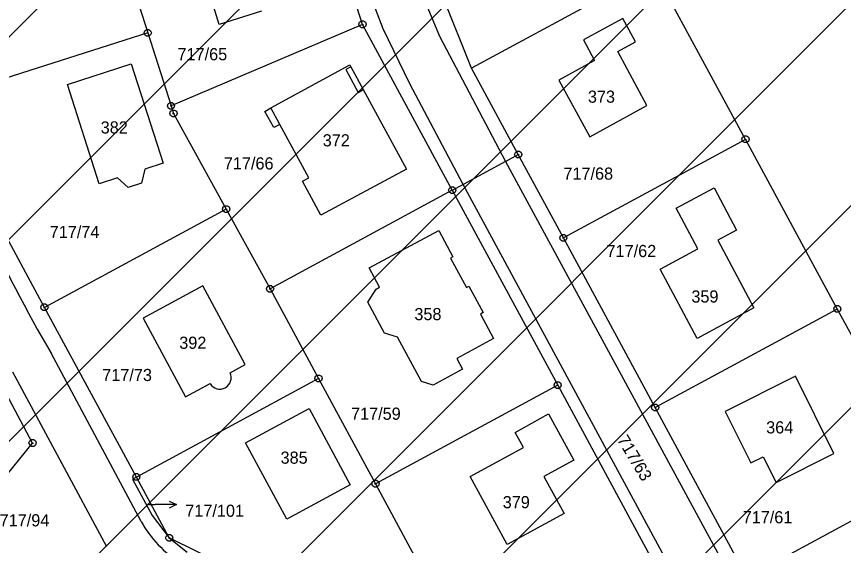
# Model space of a CAD drawing. Extents: x -593358 to -590116, y -1072518 to -1068420.
# Drawn here: x -591378.7 to -591263, y -1070308.2 to -1070234.1 of the extents above; entities that cross this region are included whole.
import ezdxf

# ---------------------------------------------------------------- set-up
doc = ezdxf.new("R2010")
doc.units = 0
for name, color, linetype in [('Parcela KN', 7, 'Continuous'), ('Parcelní číslo', 7, 'Continuous'), ('Parcelní číslo_stavební', 7, 'Continuous'), ('stavby - vnitřní kresba', 7, 'Continuous'), ('Vrstva 16', 7, 'Continuous'), ('Vrstva 24', 7, 'Continuous'), ('zastavitelné území', 7, 'Continuous')]:
    doc.layers.add(name, color=color, linetype=linetype)

msp = doc.modelspace()

# ---------------------------------------------------------------- linework, layer by layer
at = {"layer": 'Parcela KN'}
for p, q in [((-591330.29, -1070235.24), (-591338.49, -1070209.51)), ((-591315.03, -1070241.37), (-591326.32, -1070213.12)), ((-591327.42, -1070235.87), (-591334.44, -1070217.32)), ((-591366.12, -1070218.32), (-591360.35, -1070236.42)), ((-591350.36, -1070235.25), (-591354.32, -1070222.32)), ((-591324.18, -1070225.55), (-591319.54, -1070236.9)), ((-591289.56, -1070227.57), (-591315.03, -1070241.37)), ((-591276.69, -1070251.33), (-591289.56, -1070227.57)), ((-591344.42, -1070233.41), (-591350.36, -1070235.25)), ((-591293.87, -1070234.41), (-591299.38, -1070237.39)), ((-591292.09, -1070237.69), (-591293.87, -1070234.41)), ((-591330.29, -1070235.24), (-591357.09, -1070246.64)), ((-591317.73, -1070258.46), (-591330.29, -1070235.24)), ((-591323.68, -1070243.57), (-591327.42, -1070235.87)), ((-591360.35, -1070236.42), (-591387.97, -1070245.23)), ((-591360.35, -1070236.42), (-591357.09, -1070246.64)), ((-591319.54, -1070236.9), (-591310.26, -1070254.42)), ((-591299.38, -1070237.39), (-591297.83, -1070240.31)), ((-591294.55, -1070239.02), (-591292.09, -1070237.69)), ((-591290.52, -1070246.59), (-591294.55, -1070239.02)), ((-591371.61, -1070243.64), (-591362.67, -1070240.78)), ((-591362.67, -1070240.78), (-591358.22, -1070254.66)), ((-591297.83, -1070240.31), (-591302.82, -1070243.03)), ((-591343.12, -1070246.91), (-591332.06, -1070240.92)), ((-591332.06, -1070240.92), (-591331.92, -1070241.17)), ((-591331.92, -1070241.17), (-591330.19, -1070244.37)), ((-591308.49, -1070253.46), (-591315.03, -1070241.37)), ((-591302.82, -1070243.03), (-591298.49, -1070250.97)), ((-591367.15, -1070257.53), (-591371.61, -1070243.64)), ((-591316.22, -1070257.64), (-591323.68, -1070243.57)), ((-591330.19, -1070244.37), (-591324.16, -1070255.52)), ((-591298.49, -1070250.97), (-591290.52, -1070246.59)), ((-591357.09, -1070246.64), (-591356.75, -1070247.7)), ((-591356.75, -1070247.7), (-591349.38, -1070261.09)), ((-591343.96, -1070247.41), (-591343.12, -1070246.91)), ((-591342.72, -1070249.69), (-591343.96, -1070247.41)), ((-591341.86, -1070249.24), (-591342.72, -1070249.69)), ((-591337.81, -1070256.71), (-591341.86, -1070249.24)), ((-591276.69, -1070251.33), (-591302.18, -1070265.12)), ((-591276.69, -1070251.33), (-591263.84, -1070275.07)), ((-591310.26, -1070254.42), (-591308.49, -1070253.46)), ((-591302.18, -1070265.12), (-591308.49, -1070253.46)), ((-591358.22, -1070254.66), (-591360.78, -1070255.48)), ((-591310.26, -1070254.42), (-591316.22, -1070257.64)), ((-591360.78, -1070255.48), (-591361.21, -1070257.46)), ((-591324.16, -1070255.52), (-591336.12, -1070261.92)), ((-591364.6, -1070256.71), (-591367.15, -1070257.53)), ((-591363.11, -1070258.07), (-591364.6, -1070256.71)), ((-591338.69, -1070257.18), (-591337.81, -1070256.71)), ((-591374.81, -1070274.84), (-591383.9, -1070258.05)), ((-591361.21, -1070257.46), (-591363.11, -1070258.07)), ((-591336.12, -1070261.92), (-591338.69, -1070257.18)), ((-591317.73, -1070258.46), (-591316.22, -1070257.64)), ((-591284.08, -1070317.03), (-591316.22, -1070257.64)), ((-591286.4, -1070260.96), (-591281.09, -1070258.13)), ((-591281.09, -1070258.13), (-591277.95, -1070264.03)), ((-591317.73, -1070258.46), (-591343.23, -1070272.26)), ((-591317.73, -1070258.46), (-591302.97, -1070285.72)), ((-591349.38, -1070261.09), (-591374.81, -1070274.84)), ((-591349.38, -1070261.09), (-591343.23, -1070272.26)), ((-591283.35, -1070266.65), (-591286.4, -1070260.96)), ((-591376.47, -1070293.83), (-591393.59, -1070262.18)), ((-591329.35, -1070269.33), (-591319.63, -1070264.06)), ((-591319.63, -1070264.06), (-591317.64, -1070267.75)), ((-591289.33, -1070288.87), (-591302.18, -1070265.12)), ((-591277.95, -1070264.03), (-591280.57, -1070265.43)), ((-591280.57, -1070265.43), (-591275.51, -1070274.91)), ((-591288.63, -1070269.48), (-591283.35, -1070266.65)), ((-591317.64, -1070267.75), (-591317.99, -1070267.94)), ((-591317.99, -1070267.94), (-591315.76, -1070272.08)), ((-591327.93, -1070272.03), (-591329.35, -1070269.33)), ((-591283.44, -1070279.18), (-591288.63, -1070269.48)), ((-591352.65, -1070271.83), (-591361.01, -1070276.33)), ((-591346.7, -1070282.84), (-591352.65, -1070271.83)), ((-591328.38, -1070272.28), (-591327.93, -1070272.03)), ((-591315.76, -1070272.08), (-591315.41, -1070271.89)), ((-591315.41, -1070271.89), (-591313.43, -1070275.57)), ((-591343.23, -1070272.26), (-591336.45, -1070284.79)), ((-591329.55, -1070274.09), (-591328.38, -1070272.28)), ((-591327.21, -1070278.43), (-591329.55, -1070274.09)), ((-591361.95, -1070298.58), (-591374.81, -1070274.84)), ((-591263.84, -1070275.07), (-591289.33, -1070288.87)), ((-591275.51, -1070274.91), (-591283.44, -1070279.18)), ((-591263.84, -1070275.07), (-591250.98, -1070298.81)), ((-591361.01, -1070276.33), (-591355.07, -1070287.36)), ((-591313.43, -1070275.57), (-591313.79, -1070275.77)), ((-591313.79, -1070275.77), (-591311.94, -1070279.2)), ((-591325.42, -1070279), (-591327.21, -1070278.43)), ((-591322.06, -1070285.22), (-591325.42, -1070279)), ((-591311.94, -1070279.2), (-591317.1, -1070281.99)), ((-591361.26, -1070304.81), (-591373.89, -1070281.25)), ((-591317.1, -1070281.99), (-591316.29, -1070283.48)), ((-591348.84, -1070283.99), (-591346.7, -1070282.84)), ((-591316.29, -1070283.48), (-591320.4, -1070285.73)), ((-591379.3, -1070283.84), (-591366.13, -1070308.29)), ((-591336.45, -1070284.79), (-591361.95, -1070298.58)), ((-591336.45, -1070284.79), (-591328.48, -1070299.52)), ((-591269.71, -1070284.48), (-591279.54, -1070289.4)), ((-591264.33, -1070295.31), (-591269.71, -1070284.48)), ((-591355.07, -1070287.36), (-591351.63, -1070285.5)), ((-591302.97, -1070285.72), (-591328.48, -1070299.52)), ((-591320.4, -1070285.73), (-591322.06, -1070285.22)), ((-591302.97, -1070285.72), (-591288.22, -1070312.99)), ((-591346.66, -1070293.79), (-591337.77, -1070289.01)), ((-591337.77, -1070289.01), (-591332.02, -1070299.66)), ((-591276.48, -1070312.62), (-591289.33, -1070288.87)), ((-591279.54, -1070289.4), (-591275.94, -1070296.58)), ((-591308.93, -1070292.34), (-591304.27, -1070289.74)), ((-591304.27, -1070289.74), (-591300.73, -1070296.21)), ((-591307.78, -1070294.44), (-591308.93, -1070292.34)), ((-591381.06, -1070299.45), (-591376.47, -1070293.83)), ((-591340.88, -1070304.46), (-591346.66, -1070293.79)), ((-591315.25, -1070298.53), (-591307.78, -1070294.44)), ((-591300.73, -1070296.21), (-591304.93, -1070298.53)), ((-591275.94, -1070296.58), (-591274.23, -1070295.74)), ((-591274.23, -1070295.74), (-591272.4, -1070299.36)), ((-591272.4, -1070299.36), (-591264.33, -1070295.31)), ((-591361.95, -1070298.58), (-591362.49, -1070298.87)), ((-591357.34, -1070307.11), (-591361.95, -1070298.58)), ((-591310.04, -1070308.03), (-591315.25, -1070298.53)), ((-591304.93, -1070298.53), (-591302.09, -1070303.67)), ((-591362.49, -1070298.87), (-591360.69, -1070302.22)), ((-591332.02, -1070299.66), (-591340.88, -1070304.46)), ((-591328.48, -1070299.52), (-591313.73, -1070326.79)), ((-591250.98, -1070298.81), (-591276.48, -1070312.62)), ((-591360.69, -1070302.22), (-591359.74, -1070303.99)), ((-591359.74, -1070303.99), (-591357.34, -1070307.11)), ((-591302.09, -1070303.67), (-591310.04, -1070308.03)), ((-591315.34, -1070327.66), (-591357.34, -1070307.11)), ((-591357.34, -1070307.11), (-591354.86, -1070309.12))]:
    msp.add_line(p, q, dxfattribs=at)
for centre, radius, start, end in [((-591198.98, -1070178.927), 202.641, 198.6592, 210.3277), ((-591350.263, -1070284.693), 1.587, 210.57505, 26.2711), ((-591347.632, -1070297.363), 15.531, 208.65478, 238.39719)]:
    msp.add_arc(centre, radius, start, end, dxfattribs=at)
at = {"layer": 'stavby - vnitřní kresba'}
for p, q in [((-591331.92, -1070241.17), (-591332.62, -1070241.55)), ((-591332.62, -1070241.55), (-591330.9, -1070244.75)), ((-591330.9, -1070244.75), (-591330.19, -1070244.37)), ((-591341.86, -1070249.24), (-591343.12, -1070246.91)), ((-591310.26, -1070254.42), (-591265.03, -1070337.88))]:
    msp.add_line(p, q, dxfattribs=at)
at = {"layer": 'Vrstva 16'}
for p in [(-591360.27, -1070302.43), (-591356.34, -1070302.446)]:
    msp.add_line(p, (-591359.34, -1070302.43), dxfattribs=at)
msp.add_lwpolyline([(-591357.337, -1070301.941), (-591356.34, -1070302.446), (-591357.343, -1070302.941)], dxfattribs=at)
at = {"layer": 'Vrstva 24'}
for p, q in [((-591330.41, -1070235.24), (-591330.17, -1070235.24)), ((-591360.47, -1070236.42), (-591360.23, -1070236.42)), ((-591357.21, -1070246.64), (-591356.97, -1070246.64)), ((-591356.87, -1070247.7), (-591356.63, -1070247.7)), ((-591276.81, -1070251.33), (-591276.57, -1070251.33)), ((-591308.61, -1070253.46), (-591308.37, -1070253.46)), ((-591317.85, -1070258.46), (-591317.61, -1070258.46)), ((-591349.5, -1070261.09), (-591349.26, -1070261.09)), ((-591302.3, -1070265.12), (-591302.06, -1070265.12)), ((-591343.35, -1070272.26), (-591343.11, -1070272.26)), ((-591374.93, -1070274.84), (-591374.69, -1070274.84)), ((-591263.96, -1070275.07), (-591263.72, -1070275.07)), ((-591336.57, -1070284.79), (-591336.33, -1070284.79)), ((-591303.09, -1070285.72), (-591302.85, -1070285.72)), ((-591289.45, -1070288.87), (-591289.21, -1070288.87)), ((-591376.59, -1070293.83), (-591376.35, -1070293.83)), ((-591362.07, -1070298.58), (-591361.83, -1070298.58)), ((-591328.6, -1070299.52), (-591328.36, -1070299.52)), ((-591357.46, -1070307.11), (-591357.22, -1070307.11))]:
    msp.add_line(p, q, dxfattribs=at)
for points in [[(-591330.14, -1070234.76), (-591329.89, -1070234.94), (-591329.79, -1070235.23), (-591329.89, -1070235.52), (-591330.14, -1070235.7), (-591330.45, -1070235.7), (-591330.7, -1070235.52), (-591330.8, -1070235.23), (-591330.7, -1070234.94), (-591330.45, -1070234.76)], [(-591360.2, -1070235.94), (-591359.95, -1070236.12), (-591359.85, -1070236.41), (-591359.95, -1070236.7), (-591360.2, -1070236.88), (-591360.51, -1070236.88), (-591360.76, -1070236.7), (-591360.86, -1070236.41), (-591360.76, -1070236.12), (-591360.51, -1070235.94)], [(-591356.94, -1070246.16), (-591356.69, -1070246.34), (-591356.59, -1070246.63), (-591356.69, -1070246.92), (-591356.94, -1070247.1), (-591357.25, -1070247.1), (-591357.5, -1070246.92), (-591357.6, -1070246.63), (-591357.5, -1070246.34), (-591357.25, -1070246.16)], [(-591356.6, -1070247.22), (-591356.35, -1070247.4), (-591356.25, -1070247.69), (-591356.35, -1070247.98), (-591356.6, -1070248.16), (-591356.91, -1070248.16), (-591357.16, -1070247.98), (-591357.26, -1070247.69), (-591357.16, -1070247.4), (-591356.91, -1070247.22)], [(-591276.54, -1070250.85), (-591276.29, -1070251.03), (-591276.19, -1070251.32), (-591276.29, -1070251.61), (-591276.54, -1070251.79), (-591276.85, -1070251.79), (-591277.1, -1070251.61), (-591277.2, -1070251.32), (-591277.1, -1070251.03), (-591276.85, -1070250.85)], [(-591308.34, -1070252.98), (-591308.09, -1070253.16), (-591307.99, -1070253.45), (-591308.09, -1070253.74), (-591308.34, -1070253.92), (-591308.65, -1070253.92), (-591308.9, -1070253.74), (-591309, -1070253.45), (-591308.9, -1070253.16), (-591308.65, -1070252.98)], [(-591317.58, -1070257.98), (-591317.33, -1070258.16), (-591317.23, -1070258.45), (-591317.33, -1070258.74), (-591317.58, -1070258.92), (-591317.89, -1070258.92), (-591318.14, -1070258.74), (-591318.24, -1070258.45), (-591318.14, -1070258.16), (-591317.89, -1070257.98)], [(-591349.23, -1070260.61), (-591348.98, -1070260.79), (-591348.88, -1070261.08), (-591348.98, -1070261.37), (-591349.23, -1070261.55), (-591349.54, -1070261.55), (-591349.79, -1070261.37), (-591349.89, -1070261.08), (-591349.79, -1070260.79), (-591349.54, -1070260.61)], [(-591302.03, -1070264.64), (-591301.78, -1070264.82), (-591301.68, -1070265.11), (-591301.78, -1070265.4), (-591302.03, -1070265.58), (-591302.34, -1070265.58), (-591302.59, -1070265.4), (-591302.69, -1070265.11), (-591302.59, -1070264.82), (-591302.34, -1070264.64)], [(-591343.08, -1070271.78), (-591342.83, -1070271.96), (-591342.73, -1070272.25), (-591342.83, -1070272.54), (-591343.08, -1070272.72), (-591343.39, -1070272.72), (-591343.64, -1070272.54), (-591343.74, -1070272.25), (-591343.64, -1070271.96), (-591343.39, -1070271.78)], [(-591374.66, -1070274.36), (-591374.41, -1070274.54), (-591374.31, -1070274.83), (-591374.41, -1070275.12), (-591374.66, -1070275.3), (-591374.97, -1070275.3), (-591375.22, -1070275.12), (-591375.32, -1070274.83), (-591375.22, -1070274.54), (-591374.97, -1070274.36)], [(-591263.69, -1070274.59), (-591263.44, -1070274.77), (-591263.34, -1070275.06), (-591263.44, -1070275.35), (-591263.69, -1070275.53), (-591264, -1070275.53), (-591264.25, -1070275.35), (-591264.35, -1070275.06), (-591264.25, -1070274.77), (-591264, -1070274.59)], [(-591336.3, -1070284.31), (-591336.05, -1070284.49), (-591335.95, -1070284.78), (-591336.05, -1070285.07), (-591336.3, -1070285.25), (-591336.61, -1070285.25), (-591336.86, -1070285.07), (-591336.96, -1070284.78), (-591336.86, -1070284.49), (-591336.61, -1070284.31)], [(-591302.82, -1070285.24), (-591302.57, -1070285.42), (-591302.47, -1070285.71), (-591302.57, -1070286), (-591302.82, -1070286.18), (-591303.13, -1070286.18), (-591303.38, -1070286), (-591303.48, -1070285.71), (-591303.38, -1070285.42), (-591303.13, -1070285.24)], [(-591289.18, -1070288.39), (-591288.93, -1070288.57), (-591288.83, -1070288.86), (-591288.93, -1070289.15), (-591289.18, -1070289.33), (-591289.49, -1070289.33), (-591289.74, -1070289.15), (-591289.84, -1070288.86), (-591289.74, -1070288.57), (-591289.49, -1070288.39)], [(-591376.32, -1070293.35), (-591376.07, -1070293.53), (-591375.97, -1070293.82), (-591376.07, -1070294.11), (-591376.32, -1070294.29), (-591376.63, -1070294.29), (-591376.88, -1070294.11), (-591376.98, -1070293.82), (-591376.88, -1070293.53), (-591376.63, -1070293.35)], [(-591361.8, -1070298.1), (-591361.55, -1070298.28), (-591361.45, -1070298.57), (-591361.55, -1070298.86), (-591361.8, -1070299.04), (-591362.11, -1070299.04), (-591362.36, -1070298.86), (-591362.46, -1070298.57), (-591362.36, -1070298.28), (-591362.11, -1070298.1)], [(-591328.33, -1070299.04), (-591328.08, -1070299.22), (-591327.98, -1070299.51), (-591328.08, -1070299.8), (-591328.33, -1070299.98), (-591328.64, -1070299.98), (-591328.89, -1070299.8), (-591328.99, -1070299.51), (-591328.89, -1070299.22), (-591328.64, -1070299.04)], [(-591357.19, -1070306.63), (-591356.94, -1070306.81), (-591356.84, -1070307.1), (-591356.94, -1070307.39), (-591357.19, -1070307.57), (-591357.5, -1070307.57), (-591357.75, -1070307.39), (-591357.85, -1070307.1), (-591357.75, -1070306.81), (-591357.5, -1070306.63)]]:
    msp.add_lwpolyline(points, close=True, dxfattribs=at)
at = {"layer": 'zastavitelné území'}
for p, q in [((-591509.234, -1070366.46), (-591191.409, -1070048.635)), ((-591511.223, -1070396.734), (-591184.75, -1070070.261)), ((-591535.698, -1070449.493), (-591179.315, -1070093.111)), ((-591513.288, -1070455.368), (-591170.017, -1070112.097)), ((-591467.818, -1070438.181), (-591160.472, -1070130.836)), ((-591375.97, -1070374.618), (-591146.829, -1070145.477)), ((-591336.028, -1070362.96), (-591136.942, -1070163.875))]:
    msp.add_line(p, q, dxfattribs=at)

# ---------------------------------------------------------------- texts
at = {"layer": 'Parcelní číslo'}
for s, height, p in [('717/65', 1.7, (-591356.191, -1070240.26)), ('717/66', 1.7, (-591349.704, -1070255.54)), ('717/68', 1.7, (-591302.174, -1070256.97)), ('717/74', 1.7, (-591374.074, -1070265.14)), ('717/62', 1.7, (-591296.138, -1070267.8)), ('717/73', 1.7, (-591366.721, -1070285.15)), ('717/59', 1.7, (-591331.901, -1070290.57)), ('717/101', 0.1, (-591360.488, -1070302.43)), ('717/61', 1.7, (-591277.086, -1070305.06)), ('717/94', 1.7, (-591381.084, -1070305.49))]:
    msp.add_text(s, height=height, dxfattribs=at).set_placement(p)
msp.add_text('717/63', height=1.7, rotation=300.91743, dxfattribs=at).set_placement((-591294.713, -1070293.356))
at = {"layer": 'Parcelní číslo_stavební'}
for s, p in [('373', (-591298.748, -1070246.2)), ('382', (-591366.942, -1070250.51)), ('372', (-591335.865, -1070252.31)), ('359', (-591284.268, -1070274.17)), ('358', (-591323.038, -1070276.63)), ('392', (-591355.945, -1070280.64)), ('364', (-591273.801, -1070292.48)), ('385', (-591341.765, -1070296.72)), ('379', (-591310.671, -1070302.95))]:
    msp.add_text(s, height=1.7, dxfattribs=at).set_placement(p)
at = {"layer": 'Vrstva 16'}
msp.add_text('717/101', height=1.7, dxfattribs=at).set_placement((-591355.103, -1070304.15))

doc.saveas('drawing.dxf')
